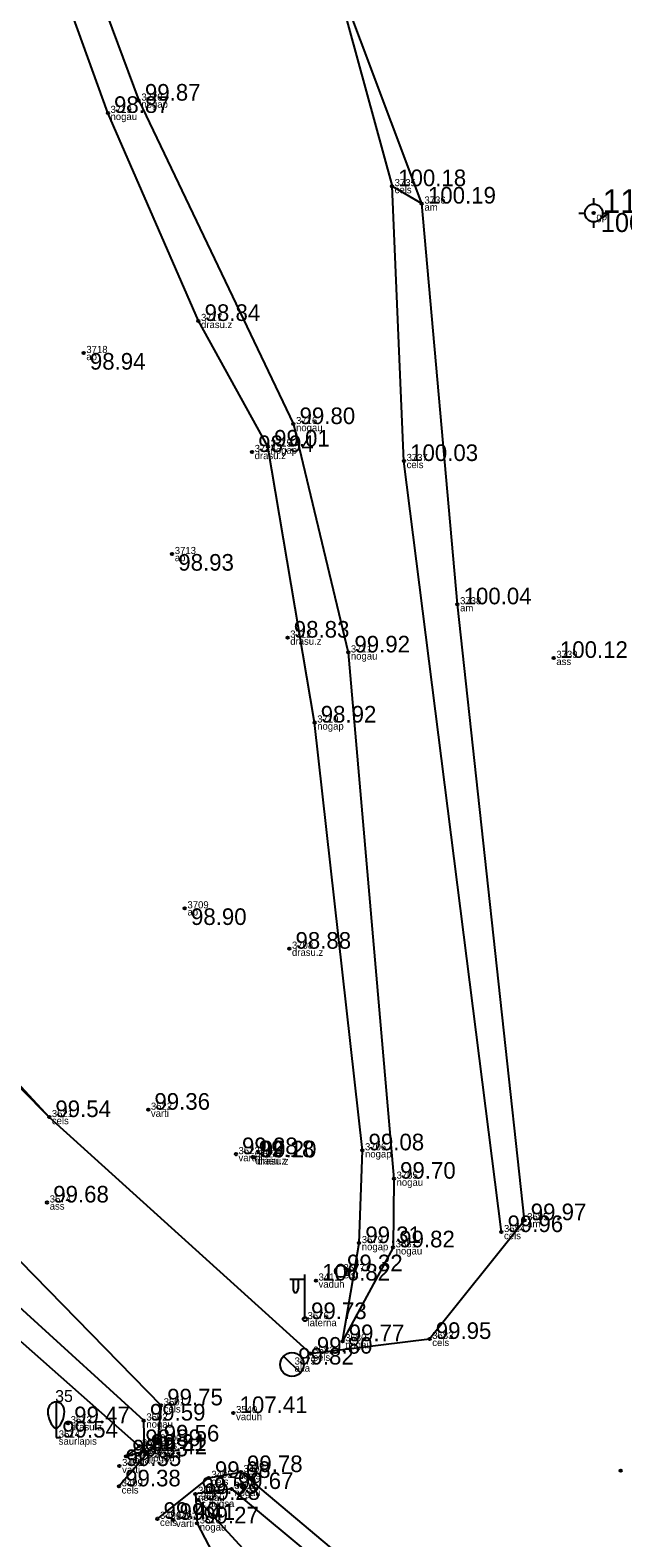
# Model space of a CAD drawing. Extents: x 614911 to 615803, y 262110 to 264311.
# Drawn here: x 615587.7 to 615612.7, y 264118.5 to 264182 of the extents above; entities that cross this region are included whole.
import ezdxf

# ---------------------------------------------------------------- set-up
doc = ezdxf.new("R2010")
doc.units = 0
for name, color, linetype in [('Level 1', 7, 'Continuous'), ('Level 12', 7, 'Continuous'), ('Level 18', 7, 'Continuous'), ('Level 19', 7, 'Continuous'), ('Level 31', 7, 'Continuous'), ('Level 37', 7, 'Continuous'), ('Level 44', 7, 'Continuous'), ('Level 53', 7, 'Continuous'), ('Level 54', 7, 'Continuous'), ('Level 57', 7, 'Continuous'), ('Level 58', 7, 'Continuous')]:
    doc.layers.add(name, color=color, linetype=linetype)

msp = doc.modelspace()

# ---------------------------------------------------------------- linework, layer by layer
at = {"layer": 'Level 1'}
for p, q in [((615588.785, 264123.12), (615588.785, 264122.768)), ((615588.785, 264122.768), (615588.985, 264122.768))]:
    msp.add_line(p, q, dxfattribs=at)
msp.add_lwpolyline([(615588.785, 264124.268), (615588.785, 264123.12)], dxfattribs=at)
for centre, major_axis, start_param, end_param in [((615588.785, 264123.868), (0, 0.4), 0, 1.570796), ((615588.785, 264123.868), (0, -0.4), 1.570796, 3.141593), ((615589.26, 264123.891), (0, -0.943), 4.7372, 5.669711), ((615588.31, 264123.891), (0, -0.943), 0.613474, 1.545985)]:
    msp.add_ellipse(centre, major_axis=major_axis, ratio=0.875, start_param=start_param, end_param=end_param, dxfattribs=at)
at = {"layer": 'Level 12'}
msp.add_line((615598.361, 264126.192), (615599.079, 264125.496), dxfattribs=at)
msp.add_circle((615598.72, 264125.844), 0.5, dxfattribs=at)
at = {"layer": 'Level 18'}
msp.add_circle((615600.779, 264129.773), 0.25, dxfattribs=at)
at = {"layer": 'Level 19'}
for p, q in [((615611.43, 264174.719), (615611.43, 264174.969)), ((615610.805, 264174.344), (615611.055, 264174.344)), ((615611.805, 264174.344), (615612.055, 264174.344)), ((615611.43, 264173.719), (615611.43, 264173.969))]:
    msp.add_line(p, q, dxfattribs=at)
for radius in [0.375, 0.05]:
    msp.add_circle((615611.43, 264174.344), radius, dxfattribs=at)
at = {"layer": 'Level 31'}
for points in [[(615586.835, 264187.816), (615584.099, 264192.736), (615568, 264210.39), (615561.107, 264218.459), (615550.946, 264229.693), (615551.547, 264230.882), (615553.756, 264232.003), (615571.747, 264213.885), (615585.706, 264197.812), (615588.191, 264195.108), (615589.392, 264186.838), (615592.266, 264179.078), (615598.78, 264165.455), (615601.089, 264155.836), (615603.013, 264133.671), (615602.976, 264130.78), (615600.849, 264126.828)], [(615600.849, 264126.828), (615601.549, 264130.958), (615601.685, 264134.866), (615599.671, 264152.885), (615597.708, 264164.507), (615594.779, 264169.798), (615590.966, 264178.56), (615588.015, 264186.729), (615586.483, 264191.829), (615585.159, 264194.038), (615568.866, 264211.337), (615556.688, 264224.915), (615551.999, 264230.205)], [(615562.249, 264162.189), (615577.05, 264148.632), (615588.494, 264136.267)], [(615591.734, 264121.976), (615592.514, 264122.204), (615592.475, 264123.485), (615582.615, 264132.468), (615577.134, 264138.567), (615571.697, 264144.459), (615562.86, 264151.976), (615561.083, 264151.838)], [(615562.117, 264150.678), (615570.639, 264143.48), (615576.105, 264137.106), (615582.009, 264131.495), (615592.285, 264122.411), (615591.734, 264121.976)], [(615605.825, 264108.936), (615601.091, 264113.26), (615594.772, 264120.142)]]:
    msp.add_lwpolyline(points, dxfattribs=at)
msp.add_lwpolyline([(615607.04, 264107.919), (615607.587, 264109.612), (615603.897, 264114.182), (615596.179, 264120.603), (615594.653, 264120.395), (615594.723, 264119.151), (615595.527, 264117.618), (615597.123, 264115.642), (615599.539, 264112.518), (615602.213, 264110.018), (615604.727, 264107.162)], close=True, dxfattribs=at)
at = {"layer": 'Level 37'}
msp.add_line((615600.319, 264185.074), (615602.933, 264175.475), dxfattribs=at)
for points in [[(615557.255, 264165.996), (615560.766, 264162.719), (615577.593, 264147.263), (615588.494, 264136.267), (615599.506, 264126.302), (615604.516, 264126.922), (615608.515, 264131.923), (615605.689, 264157.864), (615604.187, 264174.742), (615600.319, 264185.074), (615597.633, 264190.544), (615588.228, 264200.318), (615573, 264216.061), (615549.842, 264240.316), (615534.253, 264256.654), (615518.861, 264272.941)], [(615607.539, 264131.423), (615603.436, 264163.899), (615602.933, 264175.475), (615604.187, 264174.742)], [(615560.743, 264152.028), (615562.228, 264152.48), (615564.112, 264152.207), (615572.495, 264144.611), (615583.697, 264133.847), (615593.206, 264124.124), (615593.057, 264122.602), (615591.434, 264120.712)], [(615593.05, 264119.345), (615595.215, 264121.067), (615596.566, 264121.315), (615604.356, 264114.76), (615607.259, 264111.436), (615610.776, 264107.826), (615610.595, 264105.634), (615611.39, 264101.136)]]:
    msp.add_lwpolyline(points, dxfattribs=at)
at = {"layer": 'Level 44'}
for p, q in [((615599.264, 264127.757), (615599.264, 264129.64)), ((615599.264, 264129.42), (615598.629, 264129.42)), ((615598.764, 264129.42), (615598.764, 264129.028)), ((615598.974, 264129.42), (615598.974, 264129.028))]:
    msp.add_line(p, q, dxfattribs=at)
msp.add_circle((615599.264, 264127.757), 0.09, dxfattribs=at)
msp.add_ellipse((615598.869, 264129.028), major_axis=(0, 0.151), ratio=0.695971, start_param=1.570796, end_param=4.712389, dxfattribs=at)
at = {"layer": 'Level 57'}
for centre in [(615590.966, 264178.56), (615592.266, 264179.078), (615602.933, 264175.475), (615604.187, 264174.742), (615594.779, 264169.798), (615589.948, 264168.448), (615598.78, 264165.455), (615597.708, 264164.507), (615597.037, 264164.278), (615603.436, 264163.899), (615593.672, 264159.981), (615605.689, 264157.864), (615598.535, 264156.46), (615601.089, 264155.836), (615609.744, 264155.606), (615599.671, 264152.885), (615594.206, 264145.058), (615598.608, 264143.358), (615592.666, 264136.576), (615588.494, 264136.267), (615596.356, 264134.705), (615601.685, 264134.866), (615597.061, 264134.579), (615597.147, 264134.567), (615603.013, 264133.671), (615588.405, 264132.669), (615608.515, 264131.923), (615601.549, 264130.958), (615607.539, 264131.423), (615602.976, 264130.78), (615599.727, 264129.381), (615600.849, 264126.828), (615604.516, 264126.922), (615599.506, 264126.302), (615593.206, 264124.124), (615589.288, 264123.371), (615592.475, 264123.485), (615596.253, 264123.8), (615593.057, 264122.602), (615591.734, 264121.976), (615592.285, 264122.411), (615592.514, 264122.204), (615592.546, 264122.064), (615591.453, 264121.569), (615612.567, 264121.379), (615591.434, 264120.712), (615595.215, 264121.067), (615596.566, 264121.315), (615594.653, 264120.395), (615594.772, 264120.142), (615596.179, 264120.603), (615593.05, 264119.345), (615593.725, 264119.299), (615594.723, 264119.151)]:
    msp.add_circle(centre, 0.05, dxfattribs=at)
at = {"layer": 'Level 58'}
for centre in [(615590.966, 264178.56), (615592.266, 264179.078), (615602.933, 264175.475), (615604.187, 264174.742), (615594.779, 264169.798), (615589.948, 264168.448), (615598.78, 264165.455), (615597.708, 264164.507), (615597.037, 264164.278), (615603.436, 264163.899), (615593.672, 264159.981), (615605.689, 264157.864), (615598.535, 264156.46), (615601.089, 264155.836), (615609.744, 264155.606), (615599.671, 264152.885), (615594.206, 264145.058), (615598.608, 264143.358), (615592.666, 264136.576), (615588.494, 264136.267), (615596.356, 264134.705), (615601.685, 264134.866), (615597.061, 264134.579), (615597.147, 264134.567), (615603.013, 264133.671), (615588.405, 264132.669), (615608.515, 264131.923), (615601.549, 264130.958), (615607.539, 264131.423), (615602.976, 264130.78), (615599.727, 264129.381), (615600.849, 264126.828), (615604.516, 264126.922), (615599.506, 264126.302), (615593.206, 264124.124), (615589.288, 264123.371), (615592.475, 264123.485), (615596.253, 264123.8), (615593.057, 264122.602), (615591.734, 264121.976), (615592.285, 264122.411), (615592.514, 264122.204), (615592.546, 264122.064), (615591.453, 264121.569), (615612.567, 264121.379), (615591.434, 264120.712), (615595.215, 264121.067), (615596.566, 264121.315), (615594.653, 264120.395), (615594.772, 264120.142), (615596.179, 264120.603), (615593.05, 264119.345), (615593.725, 264119.299), (615594.723, 264119.151)]:
    msp.add_circle(centre, 0.05, dxfattribs=at)

# ---------------------------------------------------------------- texts
at = {"layer": 'Level 1'}
msp.add_text(' 35', height=0.5, dxfattribs=at).set_placement((615588.56, 264124.268))
at = {"layer": 'Level 19'}
for s, height, p in [(' 113', 1, (615611.43, 264174.344)), (' 100.385', 0.8, (615611.43, 264173.544))]:
    msp.add_text(s, height=height, dxfattribs=at).set_placement(p)
at = {"layer": 'Level 53'}
for s, p in [(' nogap', (615592.266, 264178.778)), (' nogau', (615590.966, 264178.26)), (' cels', (615602.933, 264175.175)), (' am', (615604.187, 264174.442)), (' gp', (615611.43, 264174.044)), (' drasu.z', (615594.779, 264169.498)), (' ap', (615589.948, 264168.148)), (' nogau', (615598.78, 264165.155)), (' drasu.z', (615597.037, 264163.978)), (' nogap', (615597.708, 264164.207)), (' cels', (615603.436, 264163.599)), (' ap', (615593.672, 264159.681)), (' am', (615605.689, 264157.564)), (' drasu.z', (615598.535, 264156.16)), (' nogau', (615601.089, 264155.536)), (' ass', (615609.744, 264155.306)), (' nogap', (615599.671, 264152.585)), (' ap', (615594.206, 264144.758)), (' drasu.z', (615598.608, 264143.058)), (' cels', (615588.494, 264135.967)), (' varti', (615592.666, 264136.276)), (' varti', (615596.356, 264134.405)), (' nogap', (615601.685, 264134.566)), (' drasu.z', (615597.061, 264134.279)), (' drasu.z', (615597.147, 264134.267)), (' nogau', (615603.013, 264133.371)), (' ass', (615588.405, 264132.369)), (' am', (615608.515, 264131.623)), (' cels', (615607.539, 264131.123)), (' nogap', (615601.549, 264130.658)), (' nogau', (615602.976, 264130.48)), (' elst', (615600.779, 264129.473)), (' vaduh', (615599.727, 264129.081)), (' laterna', (615599.264, 264127.457)), (' nogau', (615600.849, 264126.528)), (' cels', (615604.516, 264126.622)), (' aka', (615598.72, 264125.544)), (' cels', (615599.506, 264126.002)), (' cels', (615593.206, 264123.824)), (' drasu.z', (615589.288, 264123.071)), (' nogau', (615592.475, 264123.185)), (' vaduh', (615596.253, 264123.5)), (' saurlapis', (615588.785, 264122.468)), (' tekne', (615592.285, 264122.111)), (' c.augsa', (615592.514, 264121.904)), (' cels', (615593.057, 264122.302)), (' varti', (615591.453, 264121.269)), (' nogau', (615591.734, 264121.676)), (' nogau', (615592.546, 264121.764)), (' cels', (615595.215, 264120.767)), (' cels', (615596.566, 264121.015)), (' cels', (615591.434, 264120.412)), (' nogau', (615594.653, 264120.095)), (' nogau', (615596.179, 264120.303)), (' c.augsa', (615594.772, 264119.842)), (' cels', (615593.05, 264119.045)), (' varti', (615593.725, 264118.999)), (' nogau', (615594.723, 264118.851))]:
    msp.add_text(s, height=0.3, dxfattribs=at).set_placement(p)
at = {"layer": 'Level 54'}
for s, p in [(' 3720', (615592.266, 264179.078)), (' 3719', (615590.966, 264178.56)), (' 3735', (615602.933, 264175.475)), (' 3736', (615604.187, 264174.742)), (' 3717', (615594.779, 264169.798)), (' 3718', (615589.948, 264168.448)), (' 3716', (615598.78, 264165.455)), (' 3714', (615597.037, 264164.278)), (' 3715', (615597.708, 264164.507)), (' 3737', (615603.436, 264163.899)), (' 3713', (615593.672, 264159.981)), (' 3738', (615605.689, 264157.864)), (' 3712', (615598.535, 264156.46)), (' 3711', (615601.089, 264155.836)), (' 3739', (615609.744, 264155.606)), (' 3710', (615599.671, 264152.885)), (' 3709', (615594.206, 264145.058)), (' 3708', (615598.608, 264143.358)), (' 3522', (615592.666, 264136.576)), (' 3521', (615588.494, 264136.267)), (' 3523', (615596.356, 264134.705)), (' 3707', (615597.061, 264134.579)), (' 3524', (615597.147, 264134.567)), (' 3706', (615601.685, 264134.866)), (' 3705', (615603.013, 264133.671)), (' 3574', (615588.405, 264132.669)), (' 3585', (615608.515, 264131.923)), (' 3584', (615607.539, 264131.423)), (' 3579', (615601.549, 264130.958)), (' 3581', (615602.976, 264130.78)), (' 3411', (615599.727, 264129.381)), (' 3577', (615600.779, 264129.773)), (' 3576', (615599.264, 264127.757)), (' 3580', (615600.849, 264126.828)), (' 3583', (615604.516, 264126.922)), (' 3582', (615599.506, 264126.302)), (' 3575', (615598.72, 264125.844)), (' 3501', (615593.206, 264124.124)), (' 3540', (615596.253, 264123.8)), (' 3513', (615589.288, 264123.371)), (' 3502', (615592.475, 264123.485)), (' 3514', (615588.785, 264122.768)), (' 3505', (615592.285, 264122.411)), (' 3500', (615593.057, 264122.602)), (' 3504', (615591.734, 264121.976)), (' 3506', (615592.514, 264122.204)), (' 3503', (615592.546, 264122.064)), (' 3498', (615591.453, 264121.569)), (' 3495', (615595.215, 264121.067)), (' 3494', (615596.566, 264121.315)), (' 3499', (615591.434, 264120.712)), (' 3509', (615596.179, 264120.603)), (' 3508', (615594.653, 264120.395)), (' 3507', (615594.772, 264120.142)), (' 3496', (615593.05, 264119.345)), (' 3497', (615593.725, 264119.299)), (' 3510', (615594.723, 264119.151))]:
    msp.add_text(s, height=0.3, dxfattribs=at).set_placement(p)
at = {"layer": 'Level 58'}
for s, p in [(' 98.87', (615590.966, 264178.56)), (' 99.87', (615592.266, 264179.078)), (' 100.18', (615602.933, 264175.475)), (' 100.19', (615604.187, 264174.742)), (' 98.84', (615594.779, 264169.798)), (' 98.94', (615589.948, 264167.748)), (' 99.80', (615598.78, 264165.455)), (' 99.01', (615597.708, 264164.507)), (' 98.94', (615597.037, 264164.278)), (' 100.03', (615603.436, 264163.899)), (' 98.93', (615593.672, 264159.281)), (' 100.04', (615605.689, 264157.864)), (' 98.83', (615598.535, 264156.46)), (' 99.92', (615601.089, 264155.836)), (' 100.12', (615609.744, 264155.606)), (' 98.92', (615599.671, 264152.885)), (' 98.90', (615594.206, 264144.358)), (' 98.88', (615598.608, 264143.358)), (' 99.36', (615592.666, 264136.576)), (' 99.54', (615588.494, 264136.267)), (' 99.28', (615596.356, 264134.705)), (' 99.08', (615601.685, 264134.866)), (' 99.18', (615597.061, 264134.579)), (' 99.20', (615597.147, 264134.567)), (' 99.70', (615603.013, 264133.671)), (' 99.68', (615588.405, 264132.669)), (' 99.97', (615608.515, 264131.923)), (' 99.31', (615601.549, 264130.958)), (' 99.96', (615607.539, 264131.423)), (' 99.82', (615602.976, 264130.78)), (' 99.32', (615600.779, 264129.773)), (' 106.82', (615599.727, 264129.381)), (' 99.73', (615599.264, 264127.757)), (' 99.77', (615600.849, 264126.828)), (' 99.95', (615604.516, 264126.922)), (' 99.82', (615598.72, 264125.844)), (' 99.80', (615599.506, 264126.302)), (' 99.75', (615593.206, 264124.124)), (' 99.47', (615589.288, 264123.371)), (' 99.59', (615592.475, 264123.485)), (' 107.41', (615596.253, 264123.8)), (' 99.54', (615588.785, 264122.768)), (' 99.56', (615593.057, 264122.602)), (' 99.33', (615591.734, 264121.976)), (' 98.89', (615592.285, 264122.411)), (' 99.31', (615592.514, 264122.204)), (' 99.42', (615592.546, 264122.064)), (' 99.35', (615591.453, 264121.569)), (' 99.78', (615596.566, 264121.315)), (' 99.38', (615591.434, 264120.712)), (' 99.68', (615595.215, 264121.067)), (' 99.53', (615594.653, 264120.395)), (' 99.28', (615594.772, 264120.142)), (' 99.67', (615596.179, 264120.603)), (' 99.40', (615593.05, 264119.345)), (' 99.41', (615593.725, 264119.299)), (' 99.27', (615594.723, 264119.151))]:
    msp.add_text(s, height=0.7, dxfattribs=at).set_placement(p)

doc.saveas('drawing.dxf')
